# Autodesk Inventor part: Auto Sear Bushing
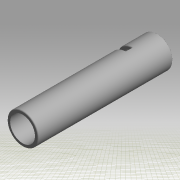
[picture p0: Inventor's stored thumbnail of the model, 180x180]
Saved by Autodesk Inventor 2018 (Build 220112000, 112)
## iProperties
Created: 2019-01
Part Number: Auto Sear Bushing
Material: Generic
Document SubType Name: Modeling
Designer: johne
Appearance: Default
Author: johne
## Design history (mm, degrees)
feature "Solid2"
body "Solid1"
